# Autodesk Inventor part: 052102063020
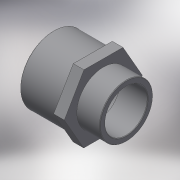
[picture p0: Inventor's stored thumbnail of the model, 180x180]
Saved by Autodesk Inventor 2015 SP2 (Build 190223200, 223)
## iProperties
Created: 2017-10
Part Number: 052102063020
Material: Generic
Description: PLASSON SOCKET NIPPLE THR-CE 75(63)-2"
Document SubType Name: Modeling
Designer: KIM
Density: 1 g/cm^3
Appearance: Default
Author: KIM
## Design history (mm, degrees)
derived "052102.ipt"
feature "Solid1::052102.ipt"
tag "TaggingFeature1"
body "Solid1"
other parameters: "d0" = 82, "d2" = 76, "d13" = 0, "d14" = 0.63, "d17" = 44, "d18" = 31.2, "d19" = 75, "d20" = 63, "d21" = 59.614, "d22" = 38, "d23" = 59.85, "d24" = 47.6912, "d25" = 26, "d26" = -44, "d_" = 63, "R_" = 59.614, "C_" = 76, "B_" = 12, "L_" = 44, "lt_" = 26, "H_" = 82, "D_" = 75, "l_" = 38
